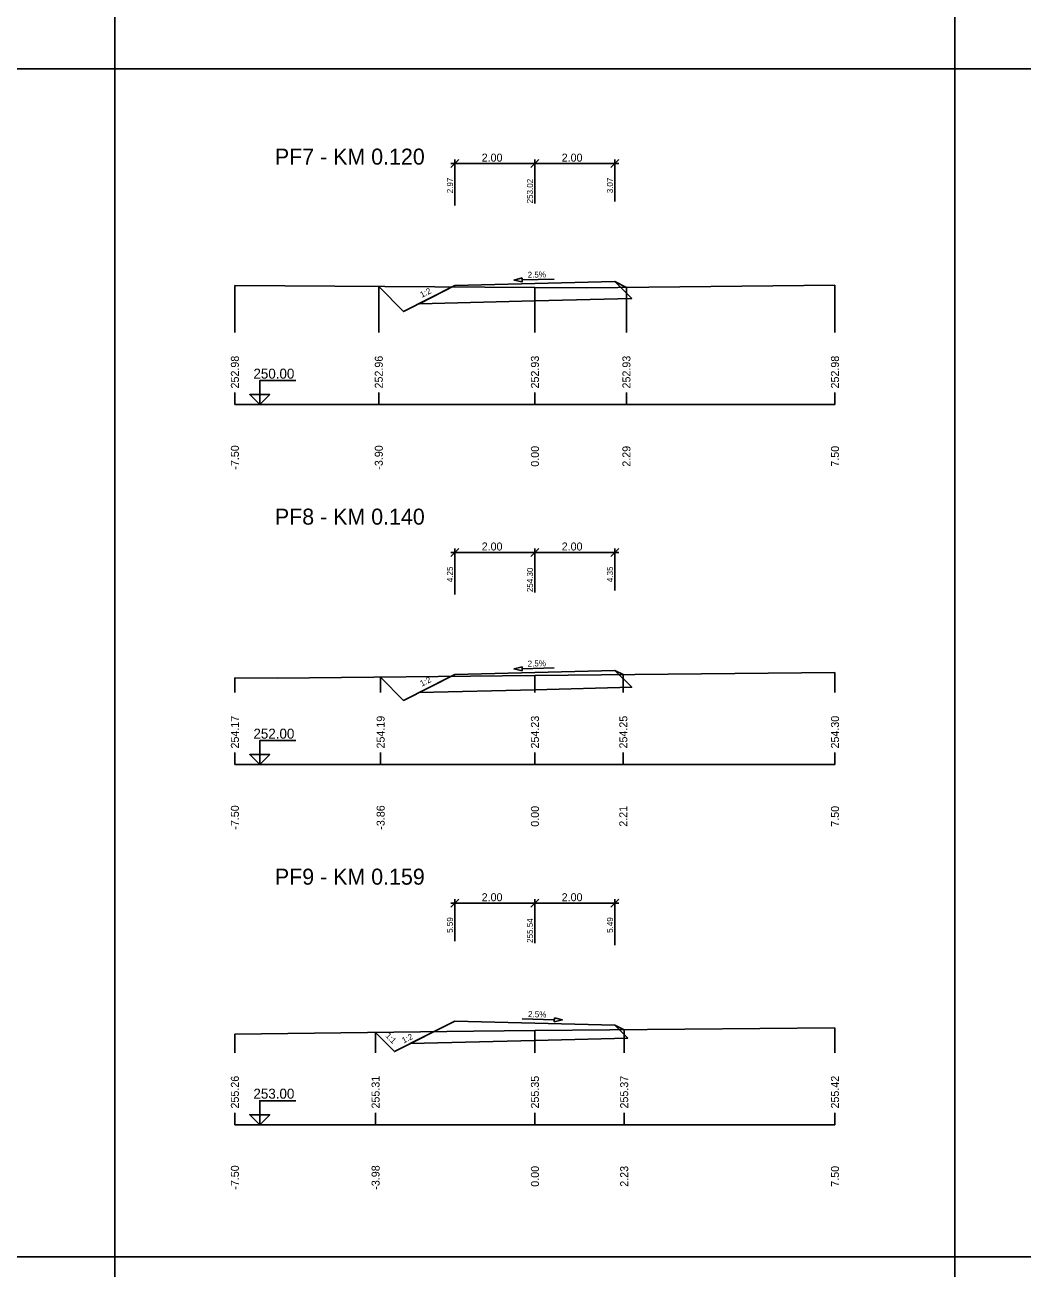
# Model space of a CAD drawing. Extents: x -1895 to 2525, y -19 to 585.
# Drawn here: x -1492.4 to -1243, y -19.1 to 293.9 of the extents above; entities that cross this region are included whole.
import ezdxf

# ---------------------------------------------------------------- set-up
doc = ezdxf.new("R2010")
doc.units = 0
for name, color, linetype in [('KOTA', 7, 'Continuous'), ('KOTA_DELKY', 7, 'Continuous'), ('KOTA_DELKY_CONT', 7, 'Continuous'), ('NS_TELESO_VOZOVKY', 7, 'Continuous'), ('NS_V_PF', 7, 'Continuous'), ('REZY_PF_PUVODNI', 7, 'Continuous'), ('SESTAVY_REZU_PF', 7, 'Continuous'), ('SKLON', 7, 'Continuous'), ('SVK', 7, 'Continuous')]:
    doc.layers.add(name, color=color, linetype=linetype)

msp = doc.modelspace()

# ---------------------------------------------------------------- linework, layer by layer
for p, q in [((-1469.95, 287.93), (-1469.95, 277.93)), ((-1469.95, 287.93), (-1469.95, 277.93)), ((-1469.95, 287.93), (-1469.95, 277.93)), ((-1469.95, 287.93), (-1469.95, 277.93)), ((-1259.95, 287.93), (-1259.95, 277.93)), ((-1259.95, 287.93), (-1259.95, 277.93)), ((-1259.95, 287.93), (-1259.95, 277.93)), ((-1259.95, 287.93), (-1259.95, 277.93)), ((-1464.95, 282.93), (-1474.95, 282.93)), ((-1464.95, 282.93), (-1474.95, 282.93)), ((-1464.95, 282.93), (-1474.95, 282.93)), ((-1464.95, 282.93), (-1474.95, 282.93)), ((-1254.95, 282.93), (-1264.95, 282.93)), ((-1254.95, 282.93), (-1264.95, 282.93)), ((-1254.95, 282.93), (-1264.95, 282.93)), ((-1254.95, 282.93), (-1264.95, 282.93)), ((-1469.95, -9.07), (-1469.95, -19.07)), ((-1469.95, -9.07), (-1469.95, -19.07)), ((-1259.95, -9.07), (-1259.95, -19.07)), ((-1259.95, -9.07), (-1259.95, -19.07)), ((-1464.95, -14.07), (-1474.95, -14.07)), ((-1464.95, -14.07), (-1474.95, -14.07)), ((-1254.95, -14.07), (-1264.95, -14.07)), ((-1254.95, -14.07), (-1264.95, -14.07))]:
    msp.add_line(p, q)
for points in [[(-1679.95, 579.93), (-1469.95, 579.93), (-1469.95, 282.93), (-1679.95, 282.93)], [(-1469.95, 579.93), (-1259.95, 579.93), (-1259.95, 282.93), (-1469.95, 282.93)], [(-1259.95, 579.93), (-1049.95, 579.93), (-1049.95, 282.93), (-1259.95, 282.93)], [(-1679.95, 282.93), (-1469.95, 282.93), (-1469.95, -14.07), (-1679.95, -14.07)], [(-1469.95, 282.93), (-1259.95, 282.93), (-1259.95, -14.07), (-1469.95, -14.07)], [(-1259.95, 282.93), (-1049.95, 282.93), (-1049.95, -14.07), (-1259.95, -14.07)]]:
    msp.add_lwpolyline(points, close=True)
at = {"layer": 'KOTA'}
for points in [[(-1433.73, 201.5), (-1436.23, 201.5), (-1433.73, 199), (-1433.73, 205), (-1424.73, 205)], [(-1433.73, 199), (-1431.23, 201.5), (-1433.73, 201.5)], [(-1433.73, 111.5), (-1436.23, 111.5), (-1433.73, 109), (-1433.73, 115), (-1424.73, 115)], [(-1433.73, 109), (-1431.23, 111.5), (-1433.73, 111.5)], [(-1433.73, 21.5), (-1436.23, 21.5), (-1433.73, 19), (-1433.73, 25), (-1424.73, 25)], [(-1433.73, 19), (-1431.23, 21.5), (-1433.73, 21.5)]]:
    msp.add_lwpolyline(points, dxfattribs=at)
at = {"layer": 'KOTA_DELKY'}
for points in [[(-1385.95, 258.25), (-1383.95, 260.25)], [(-1384.95, 248.75), (-1384.95, 260.25)], [(-1365.95, 258.25), (-1363.95, 260.25)], [(-1365.95, 258.25), (-1363.95, 260.25)], [(-1364.95, 249.25), (-1364.95, 260.25)], [(-1364.95, 249.25), (-1364.95, 260.25)], [(-1345.95, 258.25), (-1343.95, 260.25)], [(-1344.95, 249.75), (-1344.95, 260.25)], [(-1385.95, 259.25), (-1363.95, 259.25)], [(-1365.95, 259.25), (-1343.95, 259.25)], [(-1385.95, 161.04), (-1383.95, 163.04)], [(-1384.95, 151.54), (-1384.95, 163.04)], [(-1365.95, 161.04), (-1363.95, 163.04)], [(-1365.95, 161.04), (-1363.95, 163.04)], [(-1364.95, 152.04), (-1364.95, 163.04)], [(-1364.95, 152.04), (-1364.95, 163.04)], [(-1345.95, 161.04), (-1343.95, 163.04)], [(-1344.95, 152.54), (-1344.95, 163.04)], [(-1385.95, 162.04), (-1363.95, 162.04)], [(-1365.95, 162.04), (-1343.95, 162.04)], [(-1385.95, 73.36), (-1383.95, 75.36)], [(-1384.95, 64.86), (-1384.95, 75.36)], [(-1365.95, 73.36), (-1363.95, 75.36)], [(-1365.95, 73.36), (-1363.95, 75.36)], [(-1364.95, 64.36), (-1364.95, 75.36)], [(-1364.95, 64.36), (-1364.95, 75.36)], [(-1345.95, 73.36), (-1343.95, 75.36)], [(-1344.95, 63.86), (-1344.95, 75.36)], [(-1385.95, 74.36), (-1363.95, 74.36)], [(-1365.95, 74.36), (-1343.95, 74.36)]]:
    msp.add_lwpolyline(points, dxfattribs=at)
at = {"layer": 'NS_TELESO_VOZOVKY'}
for points in [[(-1364.95, 229.25), (-1344.95, 229.75), (-1344.95, 229.75), (-1340.75, 225.55), (-1364.95, 224.95), (-1393.89, 224.22), (-1384.95, 228.75), (-1384.95, 228.75), (-1364.95, 229.25)], [(-1364.95, 132.04), (-1344.95, 132.54), (-1344.95, 132.54), (-1340.75, 128.35), (-1364.95, 127.74), (-1393.89, 127.02), (-1384.95, 131.54), (-1384.95, 131.54), (-1364.95, 132.04)], [(-1364.95, 44.36), (-1344.95, 43.86), (-1344.95, 43.86), (-1341.73, 40.64), (-1364.95, 40.06), (-1396.11, 39.28), (-1384.95, 44.86), (-1384.95, 44.86), (-1364.95, 44.36)]]:
    msp.add_lwpolyline(points, dxfattribs=at)
at = {"layer": 'NS_V_PF'}
for points in [[(-1403.98, 228.56), (-1397.76, 222.27), (-1384.95, 228.75), (-1384.95, 228.75), (-1364.95, 229.25), (-1344.95, 229.75), (-1344.95, 229.75), (-1342.08, 228.31)], [(-1403.52, 130.89), (-1397.76, 125.07), (-1384.95, 131.54), (-1384.95, 131.54), (-1364.95, 132.04), (-1344.95, 132.54), (-1344.95, 132.54), (-1342.86, 131.5)], [(-1404.78, 42.05), (-1400.09, 37.29), (-1384.95, 44.86), (-1384.95, 44.86), (-1364.95, 44.36), (-1344.95, 43.86), (-1344.95, 43.86), (-1342.64, 42.71)]]:
    msp.add_lwpolyline(points, dxfattribs=at)
at = {"layer": 'REZY_PF_PUVODNI'}
for points in [[(-1439.95, 228.8), (-1364.95, 228.3), (-1351.94, 228.21), (-1289.95, 228.84)], [(-1439.95, 130.7), (-1429.35, 130.63), (-1364.95, 131.28), (-1289.95, 132.03)], [(-1439.95, 41.59), (-1380.3, 42.38), (-1364.95, 42.51), (-1289.95, 43.17)]]:
    msp.add_lwpolyline(points, dxfattribs=at)
at = {"layer": 'SESTAVY_REZU_PF'}
for points in [[(-1439.95, 199), (-1289.95, 199)], [(-1439.95, 109), (-1289.95, 109)], [(-1439.95, 19), (-1289.95, 19)]]:
    msp.add_lwpolyline(points, dxfattribs=at)
at = {"layer": 'SKLON'}
for points in [[(-1368.16, 230.67), (-1370.15, 230.12), (-1368.14, 229.67), (-1368.16, 230.67)], [(-1368.15, 230.17), (-1360.15, 230.37)], [(-1368.16, 133.47), (-1370.15, 132.92), (-1368.14, 132.47), (-1368.16, 133.47)], [(-1368.15, 132.97), (-1360.15, 133.17)], [(-1368.1, 45.44), (-1360.1, 45.24)], [(-1360.09, 45.74), (-1358.1, 45.19), (-1360.11, 44.74), (-1360.09, 45.74)]]:
    msp.add_lwpolyline(points, dxfattribs=at)
at = {"layer": 'SVK'}
for points in [[(-1439.95, 217), (-1439.95, 228.8)], [(-1403.98, 217), (-1403.98, 228.56)], [(-1289.95, 217), (-1289.95, 228.84)], [(-1364.95, 217), (-1364.95, 228.3)], [(-1342.08, 217), (-1342.08, 228.31)], [(-1439.95, 199), (-1439.95, 202)], [(-1403.98, 199), (-1403.98, 202)], [(-1364.95, 199), (-1364.95, 202)], [(-1342.08, 199), (-1342.08, 202)], [(-1289.95, 199), (-1289.95, 202)], [(-1342.86, 127), (-1342.86, 131.5)], [(-1289.95, 127), (-1289.95, 132.03)], [(-1439.95, 127), (-1439.95, 130.7)], [(-1403.52, 127), (-1403.52, 130.89)], [(-1364.95, 127), (-1364.95, 131.28)], [(-1439.95, 109), (-1439.95, 112)], [(-1403.52, 109), (-1403.52, 112)], [(-1364.95, 109), (-1364.95, 112)], [(-1342.86, 109), (-1342.86, 112)], [(-1289.95, 109), (-1289.95, 112)], [(-1439.95, 37), (-1439.95, 41.59)], [(-1404.78, 37), (-1404.78, 42.05)], [(-1364.95, 37), (-1364.95, 42.51)], [(-1342.64, 37), (-1342.64, 42.71)], [(-1289.95, 37), (-1289.95, 43.17)], [(-1439.95, 19), (-1439.95, 22)], [(-1404.78, 19), (-1404.78, 22)], [(-1364.95, 19), (-1364.95, 22)], [(-1342.64, 19), (-1342.64, 22)], [(-1289.95, 19), (-1289.95, 22)]]:
    msp.add_lwpolyline(points, dxfattribs=at)

# ---------------------------------------------------------------- texts
at = {"layer": 'KOTA'}
for s, p in [('250.00', (-1435.31, 205.5)), ('252.00', (-1435.31, 115.5)), ('253.00', (-1435.31, 25.5))]:
    msp.add_text(s, height=2.5, dxfattribs=at).set_placement(p)
at = {"layer": 'KOTA_DELKY'}
for p in [(-1378.26, 259.75), (-1358.26, 259.75), (-1378.26, 162.54), (-1358.26, 162.54), (-1378.26, 74.86), (-1358.26, 74.86)]:
    msp.add_text('2.00', height=2, dxfattribs=at).set_placement(p)
at = {"layer": 'KOTA_DELKY_CONT'}
for s, p in [('2.97', (-1385.45, 251.84)), ('253.02', (-1365.45, 249.32)), ('3.07', (-1345.45, 251.84)), ('4.25', (-1385.45, 154.63)), ('254.30', (-1365.45, 152.12)), ('4.35', (-1345.45, 154.63)), ('5.59', (-1385.45, 66.95)), ('255.54', (-1365.45, 64.44)), ('5.49', (-1345.45, 66.95))]:
    msp.add_text(s, height=1.5, rotation=90, dxfattribs=at).set_placement(p)
at = {"layer": 'SESTAVY_REZU_PF'}
for s, p in [('PF7 - KM 0.120', (-1429.95, 259)), ('PF8 - KM 0.140', (-1429.95, 169)), ('PF9 - KM 0.159', (-1429.95, 79))]:
    msp.add_text(s, height=4, dxfattribs=at).set_placement(p)
at = {"layer": 'SKLON'}
for s, rotation, p in [('2.5%', 1.4321, (-1366.75, 230.7)), ('1:2', 26.8233, (-1393.21, 225.69)), ('2.5%', 1.4321, (-1366.75, 133.5)), ('1:2', 26.8233, (-1393.21, 128.49)), ('2.5%', 358.5679, (-1366.68, 45.9)), ('1:1', 314.5713, (-1402.43, 41.1)), ('1:2', 26.5484, (-1397.76, 39.28))]:
    msp.add_text(s, height=1.5, rotation=rotation, dxfattribs=at).set_placement(p)
at = {"layer": 'SVK'}
for s, p in [(' 252.98', (-1438.95, 202.3)), (' 252.96', (-1402.98, 202.3)), (' 252.93', (-1363.95, 202.3)), (' 252.93', (-1341.08, 202.3)), (' 252.98', (-1288.95, 202.3)), (' -7.50', (-1438.95, 182)), (' -3.90', (-1402.98, 182)), ('  0.00', (-1363.95, 182)), ('  2.29', (-1341.08, 182)), ('  7.50', (-1288.95, 182)), (' 254.17', (-1438.95, 112.3)), (' 254.19', (-1402.52, 112.3)), (' 254.23', (-1363.95, 112.3)), (' 254.25', (-1341.86, 112.3)), (' 254.30', (-1288.95, 112.3)), (' -7.50', (-1438.95, 92)), (' -3.86', (-1402.52, 92)), ('  0.00', (-1363.95, 92)), ('  2.21', (-1341.86, 92)), ('  7.50', (-1288.95, 92)), (' 255.26', (-1438.95, 22.3)), (' 255.31', (-1403.78, 22.3)), (' 255.35', (-1363.95, 22.3)), (' 255.37', (-1341.64, 22.3)), (' 255.42', (-1288.95, 22.3)), (' -7.50', (-1438.95, 2)), (' -3.98', (-1403.78, 2)), ('  0.00', (-1363.95, 2)), ('  2.23', (-1341.64, 2)), ('  7.50', (-1288.95, 2))]:
    msp.add_text(s, height=2, rotation=90, dxfattribs=at).set_placement(p)

doc.saveas('drawing.dxf')
